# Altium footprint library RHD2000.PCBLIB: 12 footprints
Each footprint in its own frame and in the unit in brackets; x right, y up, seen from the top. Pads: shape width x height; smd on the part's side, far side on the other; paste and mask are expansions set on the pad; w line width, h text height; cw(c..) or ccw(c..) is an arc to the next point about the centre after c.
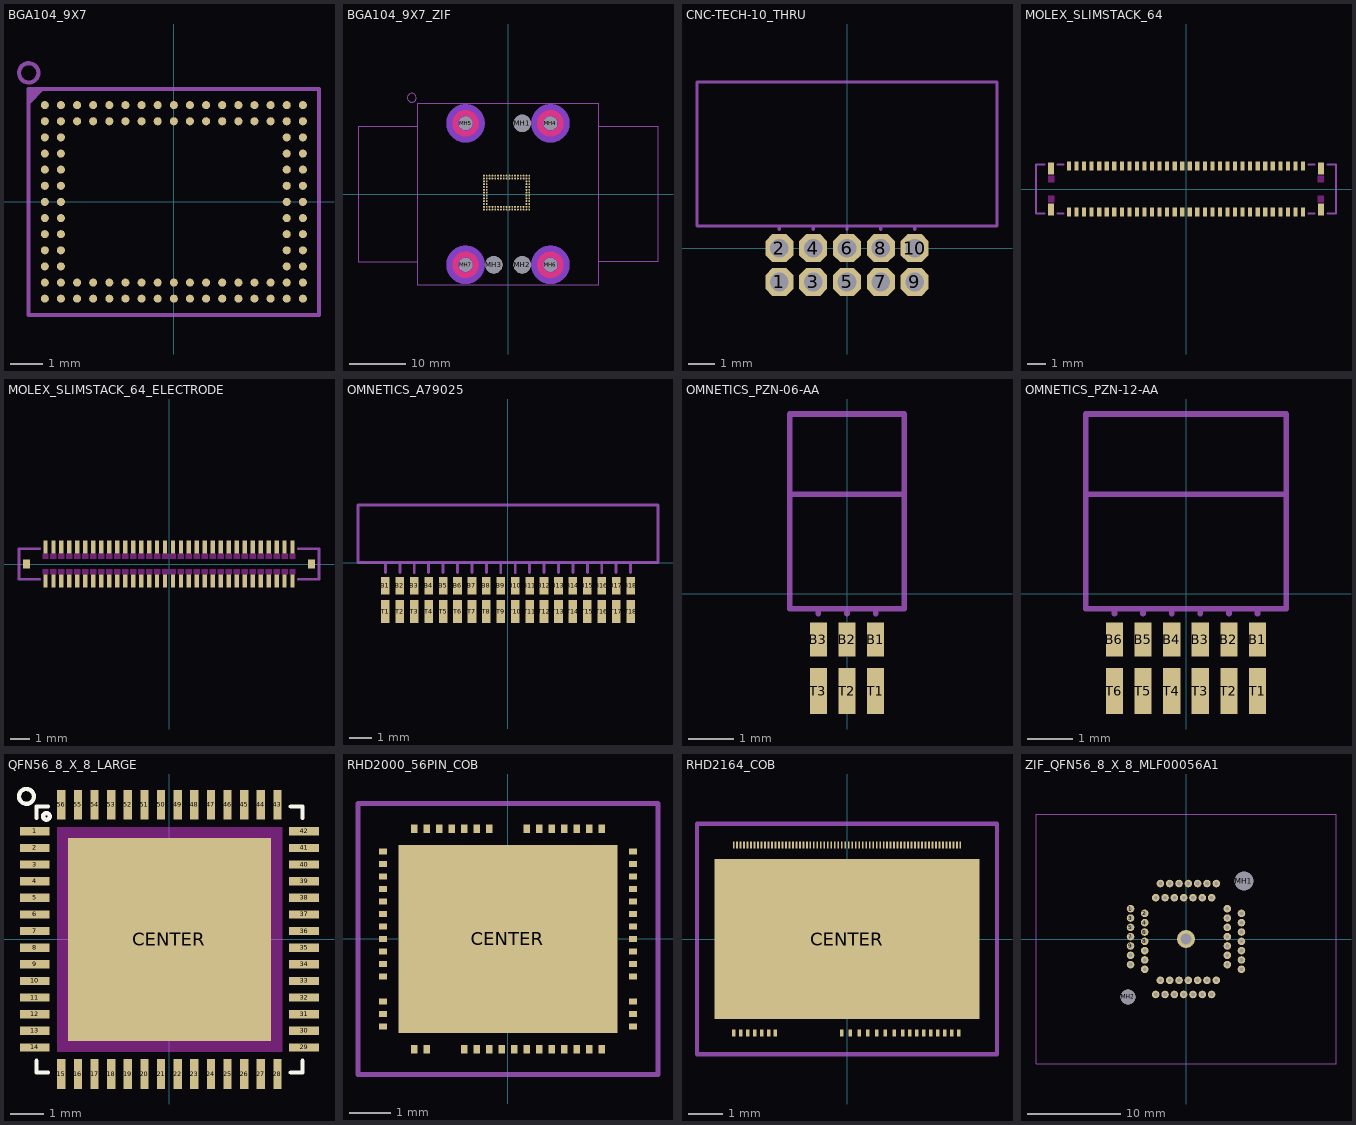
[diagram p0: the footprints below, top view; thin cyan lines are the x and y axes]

## BGA104_9X7 [mm]
pads (104):
  rrect100% 0.25x0.25 smd: A1(-4,3) A2(-3.5,3) A3(-3,3) A4(-2.5,3) A5(-2,3) A6(-1.5,3) A7(-1,3) A8(-0.5,3) A9(0,3) A10(0.5,3) A11(1,3) A12(1.5,3) A13(2,3) A14(2.5,3) A15(3,3) A16(3.5,3) A17(4,3) B1(-4,2.5) B2(-3.5,2.5) B3(-3,2.5) B4(-2.5,2.5) B5(-2,2.5) B6(-1.5,2.5) B7(-1,2.5) B8(-0.5,2.5) B9(0,2.5) B10(0.5,2.5) B11(1,2.5) B12(1.5,2.5) B13(2,2.5) B14(2.5,2.5) B15(3,2.5) B16(3.5,2.5) B17(4,2.5) C1(-4,2) C2(-3.5,2) C16(3.5,2) C17(4,2) D1(-4,1.5) D2(-3.5,1.5) D16(3.5,1.5) D17(4,1.5) E1(-4,1) E2(-3.5,1) E16(3.5,1) E17(4,1) F1(-4,0.5) F2(-3.5,0.5) F16(3.5,0.5) F17(4,0.5) G1(-4,0) G2(-3.5,0) G16(3.5,0) G17(4,0) H1(-4,-0.5) H2(-3.5,-0.5) H16(3.5,-0.5) H17(4,-0.5) J1(-4,-1) J2(-3.5,-1) J16(3.5,-1) J17(4,-1) K1(-4,-1.5) K2(-3.5,-1.5) K16(3.5,-1.5) K17(4,-1.5) L1(-4,-2) L2(-3.5,-2) L16(3.5,-2) L17(4,-2) M1(-4,-2.5) M2(-3.5,-2.5) M3(-3,-2.5) M4(-2.5,-2.5) M5(-2,-2.5) M6(-1.5,-2.5) M7(-1,-2.5) M8(-0.5,-2.5) M9(0,-2.5) M10(0.5,-2.5) M11(1,-2.5) M12(1.5,-2.5) M13(2,-2.5) M14(2.5,-2.5) M15(3,-2.5) M16(3.5,-2.5) M17(4,-2.5) N1(-4,-3) N2(-3.5,-3) N3(-3,-3) N4(-2.5,-3) N5(-2,-3) N6(-1.5,-3) N7(-1,-3) N8(-0.5,-3) N9(0,-3) N10(0.5,-3) N11(1,-3) N12(1.5,-3) N13(2,-3) N14(2.5,-3) N15(3,-3) N16(3.5,-3) N17(4,-3)
tPlace:
  circle w0.127: c-4.5,4 r0.3
  region: -4.5,3.5 -4.5,3 -4,3.5
  lines w0.127: -4.5,-3.5 -4.5,3.5 4.5,3.5 4.5,-3.5 -4.5,-3.5

## BGA104_9X7_ZIF [mil]
pads (111):
  rrect100% 13.39x13.39 smd: A1(-167.32,127.95) A2(-147.64,127.95) A3(-127.95,127.95) A4(-108.27,127.95) A5(-88.58,127.95) A6(-68.9,127.95) A7(-49.21,127.95) A8(-29.53,127.95) A9(-9.84,127.95) A10(9.84,127.95) A11(29.53,127.95) A12(49.21,127.95) A13(68.9,127.95) A14(88.58,127.95) A15(108.27,127.95) A16(127.95,127.95) A17(147.64,127.95) B1(-167.32,108.27) B2(-147.64,108.27) B3(-127.95,108.27) B4(-108.27,108.27) B5(-88.58,108.27) B6(-68.9,108.27) B7(-49.21,108.27) B8(-29.53,108.27) B9(-9.84,108.27) B10(9.84,108.27) B11(29.53,108.27) B12(49.21,108.27) B13(68.9,108.27) B14(88.58,108.27) B15(108.27,108.27) B16(127.95,108.27) B17(147.64,108.27) C1(-167.32,88.58) C2(-147.64,88.58) C16(127.95,88.58) C17(147.64,88.58) D1(-167.32,68.9) D2(-147.64,68.9) D16(127.95,68.9) D17(147.64,68.9) E1(-167.32,49.21) E2(-147.64,49.21) E16(127.95,49.21) E17(147.64,49.21) F1(-167.32,29.53) F2(-147.64,29.53) F16(127.95,29.53) F17(147.64,29.53) G1(-167.32,9.84) G2(-147.64,9.84) G16(127.95,9.84) G17(147.64,9.84) H1(-167.32,-9.84) H2(-147.64,-9.84) H16(127.95,-9.84) H17(147.64,-9.84) J1(-167.32,-29.53) J2(-147.64,-29.53) J16(127.95,-29.53) J17(147.64,-29.53) K1(-167.32,-49.21) K2(-147.64,-49.21) K16(127.95,-49.21) K17(147.64,-49.21) L1(-167.32,-68.9) L2(-147.64,-68.9) L16(127.95,-68.9) L17(147.64,-68.9) M1(-167.32,-88.58) M2(-147.64,-88.58) M3(-127.95,-88.58) M4(-108.27,-88.58) M5(-88.58,-88.58) M6(-68.9,-88.58) M7(-49.21,-88.58) M8(-29.53,-88.58) M9(-9.84,-88.58) M10(9.84,-88.58) M11(29.53,-88.58) M12(49.21,-88.58) M13(68.9,-88.58) M14(88.58,-88.58) M15(108.27,-88.58) M16(127.95,-88.58) M17(147.64,-88.58) N1(-167.32,-108.27) N2(-147.64,-108.27) N3(-127.95,-108.27) N4(-108.27,-108.27) N5(-88.58,-108.27) N6(-68.9,-108.27) N7(-49.21,-108.27) N8(-29.53,-108.27) N9(-9.84,-108.27) N10(9.84,-108.27) N11(29.53,-108.27) N12(49.21,-108.27) N13(68.9,-108.27) N14(88.58,-108.27) N15(108.27,-108.27) N16(127.95,-108.27) N17(147.64,-108.27)
  round 120 hole 120 unplated: MH1(98.43,492.13) MH2(98.43,-492.13) MH3(-98.43,-492.13)
  round 93.74 hole 93.74 unplated: MH4(295.28,492.13) MH5(-295.28,492.13) MH6(295.28,-492.13) MH7(-295.28,-492.13)
Top:
  circle w39.37: c295.28,492.13 r72.64
  circle w39.37: c-295.28,492.13 r72.64
  circle w39.37: c295.28,-492.13 r72.64
  circle w39.37: c-295.28,-492.13 r72.64
Top keep-out:
  circle w94.49: c295.28,492.13 r86.61
  circle w94.49: c-295.28,492.13 r86.61
  circle w94.49: c295.28,-492.13 r86.61
  circle w94.49: c-295.28,-492.13 r86.61
Bottom keep-out:
  circle w94.49: c295.28,492.13 r86.61
  circle w94.49: c-295.28,492.13 r86.61
  circle w94.49: c295.28,-492.13 r86.61
  circle w94.49: c-295.28,-492.13 r86.61
Top Solder:
  region: -610.24,-610.24 610.24,-610.24 610.24,610.24 -610.24,610.24
tPlace:
  circle w5: c-669.29,669.29 r31.12
  lines w5: -629.92,-472.44 -629.92,472.44 ; -629.92,-472.44 -629.92,-629.92 629.92,-629.92 629.92,-472.44 ; -629.92,-472.44 -1043.31,-472.44 -1043.31,472.44 -629.92,472.44 ; -629.92,472.44 -629.92,629.92 629.92,629.92 629.92,472.44 ; 629.92,-472.44 1043.31,-472.44 1043.31,472.44 629.92,472.44 ; 629.92,-472.44 629.92,472.44

## CNC-TECH-10_THRU [mil]
pads (10):
  oct 41.34x41.34 / inner round 38.19 / far side oct 41.34x41.34 hole 27.56: 1(-100,-50) 2(-100,0) 3(-50,-50) 4(-50,0) 5(0,-50) 6(0,0) 7(50,-50) 8(50,0) 9(100,-50) 10(100,0)
tPlace:
  lines w5: -100,27.56 -100,32.68 ; -50,27.56 -50,32.68 ; 0,27.56 0,32.68 ; 50,27.56 50,32.68 ; 100,27.56 100,32.68 ; -100,32.68 -221.46,32.68 -221.46,245.28 221.46,245.28 221.46,32.68 100,32.68 ; -100,32.68 -50,32.68 ; -50,32.68 0,32.68 ; 0,32.68 50,32.68 ; 50,32.68 100,32.68

## MOLEX_SLIMSTACK_64 [mm]
pads (68):
  rect 0.22x0.475 smd: 1(-6.2,-1.213) 2(-5.8,-1.213) 3(-5.4,-1.213) 4(-5,-1.213) 5(-4.6,-1.213) 6(-4.2,-1.213) 7(-3.8,-1.213) 8(-3.4,-1.213) 9(-3,-1.213) 10(-2.6,-1.213) 11(-2.2,-1.213) 12(-1.8,-1.213) 13(-1.4,-1.213) 14(-1,-1.213) 15(-0.6,-1.213) 16(-0.2,-1.213) 17(0.2,-1.213) 18(0.6,-1.213) 19(1,-1.213) 20(1.4,-1.213) 21(1.8,-1.213) 22(2.2,-1.213) 23(2.6,-1.213) 24(3,-1.213) 25(3.4,-1.213) 26(3.8,-1.213) 27(4.2,-1.213) 28(4.6,-1.213) 29(5,-1.213) 30(5.4,-1.213) 31(5.8,-1.213) 32(6.2,-1.213) 33(6.2,1.213) 34(5.8,1.213) 35(5.4,1.213) 36(5,1.213) 37(4.6,1.213) 38(4.2,1.213) 39(3.8,1.213) 40(3.4,1.213) 41(3,1.213) 42(2.6,1.213) 43(2.2,1.213) 44(1.8,1.213) 45(1.4,1.213) 46(1,1.213) 47(0.6,1.213) 48(0.2,1.213) 49(-0.2,1.213) 50(-0.6,1.213) 51(-1,1.213) 52(-1.4,1.213) 53(-1.8,1.213) 54(-2.2,1.213) 55(-2.6,1.213) 56(-3,1.213) 57(-3.4,1.213) 58(-3.8,1.213) 59(-4.2,1.213) 60(-4.6,1.213) 61(-5,1.213) 62(-5.4,1.213) 63(-5.8,1.213) 64(-6.2,1.213)
  rect 0.32x0.65 smd: MECH1(-7.15,1.085) MECH2(-7.15,-1.085) MECH3(7.15,1.085) MECH4(7.15,-1.085)
Top keep-out:
  region: -7.31,0.35 -7.31,0.7 -6.99,0.7 -6.99,0.35
  region: -7.31,-0.7 -7.31,-0.35 -6.99,-0.35 -6.99,-0.7
  region: 6.99,0.35 6.99,0.7 7.31,0.7 7.31,0.35
  region: 6.99,-0.7 6.99,-0.35 7.31,-0.35 7.31,-0.7
tPlace:
  lines w0.127: -7.5,-1.3 -7.95,-1.3 -7.95,1.3 -7.5,1.3 ; -6.8,-1.3 -6.5,-1.3 ; -6.8,1.3 -6.5,1.3 ; 6.5,-1.3 6.8,-1.3 ; 6.5,1.3 6.8,1.3 ; 7.5,-1.3 7.95,-1.3 7.95,1.3 7.5,1.3

## MOLEX_SLIMSTACK_64_ELECTRODE [mm]
pads (66):
  rect 0.22x0.66 smd: 1(-6.2,0.855) 2(-5.8,0.855) 3(-5.4,0.855) 4(-5,0.855) 5(-4.6,0.855) 6(-4.2,0.855) 7(-3.8,0.855) 8(-3.4,0.855) 9(-3,0.855) 10(-2.6,0.855) 11(-2.2,0.855) 12(-1.8,0.855) 13(-1.4,0.855) 14(-1,0.855) 15(-0.6,0.855) 16(-0.2,0.855) 17(0.2,0.855) 18(0.6,0.855) 19(1,0.855) 20(1.4,0.855) 21(1.8,0.855) 22(2.2,0.855) 23(2.6,0.855) 24(3,0.855) 25(3.4,0.855) 26(3.8,0.855) 27(4.2,0.855) 28(4.6,0.855) 29(5,0.855) 30(5.4,0.855) 31(5.8,0.855) 32(6.2,0.855) 33(6.2,-0.855) 34(5.8,-0.855) 35(5.4,-0.855) 36(5,-0.855) 37(4.6,-0.855) 38(4.2,-0.855) 39(3.8,-0.855) 40(3.4,-0.855) 41(3,-0.855) 42(2.6,-0.855) 43(2.2,-0.855) 44(1.8,-0.855) 45(1.4,-0.855) 46(1,-0.855) 47(0.6,-0.855) 48(0.2,-0.855) 49(-0.2,-0.855) 50(-0.6,-0.855) 51(-1,-0.855) 52(-1.4,-0.855) 53(-1.8,-0.855) 54(-2.2,-0.855) 55(-2.6,-0.855) 56(-3,-0.855) 57(-3.4,-0.855) 58(-3.8,-0.855) 59(-4.2,-0.855) 60(-4.6,-0.855) 61(-5,-0.855) 62(-5.4,-0.855) 63(-5.8,-0.855) 64(-6.2,-0.855)
  rect 0.35x0.44 smd: MECH1(-7.15,0) MECH2(7.15,0)
Top keep-out:
  region: -6.35,0.255 -6.35,0.525 -6.05,0.525 -6.05,0.255
  region: -5.95,0.255 -5.95,0.525 -5.65,0.525 -5.65,0.255
  region: -5.55,0.255 -5.55,0.525 -5.25,0.525 -5.25,0.255
  region: -5.15,0.255 -5.15,0.525 -4.85,0.525 -4.85,0.255
  region: -4.75,0.255 -4.75,0.525 -4.45,0.525 -4.45,0.255
  region: -4.35,0.255 -4.35,0.525 -4.05,0.525 -4.05,0.255
  region: -3.95,0.255 -3.95,0.525 -3.65,0.525 -3.65,0.255
  region: -3.55,0.255 -3.55,0.525 -3.25,0.525 -3.25,0.255
  region: -3.15,0.255 -3.15,0.525 -2.85,0.525 -2.85,0.255
  region: -2.75,0.255 -2.75,0.525 -2.45,0.525 -2.45,0.255
  region: -2.35,0.255 -2.35,0.525 -2.05,0.525 -2.05,0.255
  region: -1.95,0.255 -1.95,0.525 -1.65,0.525 -1.65,0.255
  region: -1.55,0.255 -1.55,0.525 -1.25,0.525 -1.25,0.255
  region: -1.15,0.255 -1.15,0.525 -0.85,0.525 -0.85,0.255
  region: -0.75,0.255 -0.75,0.525 -0.45,0.525 -0.45,0.255
  region: -0.35,0.255 -0.35,0.525 -0.05,0.525 -0.05,0.255
  region: 0.05,0.255 0.05,0.525 0.35,0.525 0.35,0.255
  region: 0.45,0.255 0.45,0.525 0.75,0.525 0.75,0.255
  region: 0.85,0.255 0.85,0.525 1.15,0.525 1.15,0.255
  region: 1.25,0.255 1.25,0.525 1.55,0.525 1.55,0.255
  region: 1.65,0.255 1.65,0.525 1.95,0.525 1.95,0.255
  region: 2.05,0.255 2.05,0.525 2.35,0.525 2.35,0.255
  region: 2.45,0.255 2.45,0.525 2.75,0.525 2.75,0.255
  region: 2.85,0.255 2.85,0.525 3.15,0.525 3.15,0.255
  region: 3.25,0.255 3.25,0.525 3.55,0.525 3.55,0.255
  region: 3.65,0.255 3.65,0.525 3.95,0.525 3.95,0.255
  region: 4.05,0.255 4.05,0.525 4.35,0.525 4.35,0.255
  region: 4.45,0.255 4.45,0.525 4.75,0.525 4.75,0.255
  region: 4.85,0.255 4.85,0.525 5.15,0.525 5.15,0.255
  region: 5.25,0.255 5.25,0.525 5.55,0.525 5.55,0.255
  region: 5.65,0.255 5.65,0.525 5.95,0.525 5.95,0.255
  region: 6.05,0.255 6.05,0.525 6.35,0.525 6.35,0.255
  region: 6.05,-0.525 6.05,-0.255 6.35,-0.255 6.35,-0.525
  region: 5.65,-0.525 5.65,-0.255 5.95,-0.255 5.95,-0.525
  region: 5.25,-0.525 5.25,-0.255 5.55,-0.255 5.55,-0.525
  region: 4.85,-0.525 4.85,-0.255 5.15,-0.255 5.15,-0.525
  region: 4.45,-0.525 4.45,-0.255 4.75,-0.255 4.75,-0.525
  region: 4.05,-0.525 4.05,-0.255 4.35,-0.255 4.35,-0.525
  region: 3.65,-0.525 3.65,-0.255 3.95,-0.255 3.95,-0.525
  region: 3.25,-0.525 3.25,-0.255 3.55,-0.255 3.55,-0.525
  region: 2.85,-0.525 2.85,-0.255 3.15,-0.255 3.15,-0.525
  region: 2.45,-0.525 2.45,-0.255 2.75,-0.255 2.75,-0.525
  region: 2.05,-0.525 2.05,-0.255 2.35,-0.255 2.35,-0.525
  region: 1.65,-0.525 1.65,-0.255 1.95,-0.255 1.95,-0.525
  region: 1.25,-0.525 1.25,-0.255 1.55,-0.255 1.55,-0.525
  region: 0.85,-0.525 0.85,-0.255 1.15,-0.255 1.15,-0.525
  region: 0.45,-0.525 0.45,-0.255 0.75,-0.255 0.75,-0.525
  region: 0.05,-0.525 0.05,-0.255 0.35,-0.255 0.35,-0.525
  region: -0.35,-0.525 -0.35,-0.255 -0.05,-0.255 -0.05,-0.525
  region: -0.75,-0.525 -0.75,-0.255 -0.45,-0.255 -0.45,-0.525
  region: -1.15,-0.525 -1.15,-0.255 -0.85,-0.255 -0.85,-0.525
  region: -1.55,-0.525 -1.55,-0.255 -1.25,-0.255 -1.25,-0.525
  region: -1.95,-0.525 -1.95,-0.255 -1.65,-0.255 -1.65,-0.525
  region: -2.35,-0.525 -2.35,-0.255 -2.05,-0.255 -2.05,-0.525
  region: -2.75,-0.525 -2.75,-0.255 -2.45,-0.255 -2.45,-0.525
  region: -3.15,-0.525 -3.15,-0.255 -2.85,-0.255 -2.85,-0.525
  region: -3.55,-0.525 -3.55,-0.255 -3.25,-0.255 -3.25,-0.525
  region: -3.95,-0.525 -3.95,-0.255 -3.65,-0.255 -3.65,-0.525
  region: -4.35,-0.525 -4.35,-0.255 -4.05,-0.255 -4.05,-0.525
  region: -4.75,-0.525 -4.75,-0.255 -4.45,-0.255 -4.45,-0.525
  region: -5.15,-0.525 -5.15,-0.255 -4.85,-0.255 -4.85,-0.525
  region: -5.55,-0.525 -5.55,-0.255 -5.25,-0.255 -5.25,-0.525
  region: -5.95,-0.525 -5.95,-0.255 -5.65,-0.255 -5.65,-0.525
  region: -6.35,-0.525 -6.35,-0.255 -6.05,-0.255 -6.05,-0.525
tPlace:
  lines w0.127: -6.5,-0.77 -7.53,-0.77 -7.53,0.77 -6.5,0.77 ; 6.5,-0.77 7.53,-0.77 7.53,0.77 6.5,0.77

## OMNETICS_A79025 [mil]
pads (36):
  rect 15x30 smd: B1(-212.5,-40) B2(-187.5,-40) B3(-162.5,-40) B4(-137.5,-40) B5(-112.5,-40) B6(-87.5,-40) B7(-62.5,-40) B8(-37.5,-40) B9(-12.5,-40) B10(12.5,-40) B11(37.5,-40) B12(62.5,-40) B13(87.5,-40) B14(112.5,-40) B15(137.5,-40) B16(162.5,-40) B17(187.5,-40) B18(212.5,-40)
  rect 15x40 smd: T1(-212.5,-85) T2(-187.5,-85) T3(-162.5,-85) T4(-137.5,-85) T5(-112.5,-85) T6(-87.5,-85) T7(-62.5,-85) T8(-37.5,-85) T9(-12.5,-85) T10(12.5,-85) T11(37.5,-85) T12(62.5,-85) T13(87.5,-85) T14(112.5,-85) T15(137.5,-85) T16(162.5,-85) T17(187.5,-85) T18(212.5,-85)
tPlace:
  lines w5: -212.5,-17.5 -212.5,0 ; -187.5,-17.5 -187.5,0 ; -162.5,-17.5 -162.5,0 ; -137.5,-17.5 -137.5,0 ; -112.5,-17.5 -112.5,0 ; -87.5,-17.5 -87.5,0 ; -62.5,-17.5 -62.5,0 ; -37.5,-17.5 -37.5,0 ; -12.5,-17.5 -12.5,0 ; 12.5,-17.5 12.5,0 ; 37.5,-17.5 37.5,0 ; 62.5,-17.5 62.5,0 ; 87.5,-17.5 87.5,0 ; 112.5,-17.5 112.5,0 ; 137.5,-17.5 137.5,0 ; 162.5,-17.5 162.5,0 ; 187.5,-17.5 187.5,0 ; 212.5,-17.5 212.5,0 ; -212.5,0 -187.5,0 ; -212.5,0 -260,0 -260,100 260,100 260,0 12.5,0 ; -187.5,0 -162.5,0 ; -162.5,0 -137.5,0 ; -137.5,0 -112.5,0 ; -112.5,0 -87.5,0 ; -87.5,0 -62.5,0 ; -62.5,0 -37.5,0 ; -37.5,0 -12.5,0 ; -12.5,0 12.5,0

## OMNETICS_PZN-06-AA [mil]
pads (6):
  rect 15x30 smd: B1(25,-40) B2(0,-40) B3(-25,-40)
  rect 15x40 smd: T1(25,-85) T2(0,-85) T3(-25,-85)
tPlace:
  lines w5: -25,-17.5 -25,-13 ; 0,-17.5 0,-13 ; 25,-17.5 25,-13 ; -50,87 -50,-13 -25,-13 ; -50,87 -50,157 50,157 50,87 ; -50,87 50,87 ; -25,-13 0,-13 ; 0,-13 25,-13 ; 25,-13 50,-13 50,87

## OMNETICS_PZN-12-AA [mil]
pads (12):
  rect 15x30 smd: B1(62.5,-40) B2(37.5,-40) B3(12.5,-40) B4(-12.5,-40) B5(-37.5,-40) B6(-62.5,-40)
  rect 15x40 smd: T1(62.5,-85) T2(37.5,-85) T3(12.5,-85) T4(-12.5,-85) T5(-37.5,-85) T6(-62.5,-85)
tPlace:
  lines w5: -62.5,-17.5 -62.5,-13 ; -37.5,-17.5 -37.5,-13 ; -12.5,-17.5 -12.5,-13 ; 12.5,-17.5 12.5,-13 ; 37.5,-17.5 37.5,-13 ; 62.5,-17.5 62.5,-13 ; -87.5,87 87.5,87 ; -87.5,87 -87.5,157 87.5,157 87.5,87 ; -87.5,87 -87.5,-13 -62.5,-13 ; -62.5,-13 -37.5,-13 ; -37.5,-13 -12.5,-13 ; -12.5,-13 12.5,-13 ; 12.5,-13 37.5,-13 ; 37.5,-13 62.5,-13 ; 62.5,-13 87.5,-13 87.5,87

## QFN56_8_X_8_LARGE [mm]
pads (57):
  rect 0.9x0.25 smd: 1(-4.05,3.25) 2(-4.05,2.75) 3(-4.05,2.25) 4(-4.05,1.75) 5(-4.05,1.25) 6(-4.05,0.75) 7(-4.05,0.25) 8(-4.05,-0.25) 9(-4.05,-0.75) 10(-4.05,-1.25) 11(-4.05,-1.75) 12(-4.05,-2.25) 13(-4.05,-2.75) 14(-4.05,-3.25) 29(4.05,-3.25) 30(4.05,-2.75) 31(4.05,-2.25) 32(4.05,-1.75) 33(4.05,-1.25) 34(4.05,-0.75) 35(4.05,-0.25) 36(4.05,0.25) 37(4.05,0.75) 38(4.05,1.25) 39(4.05,1.75) 40(4.05,2.25) 41(4.05,2.75) 42(4.05,3.25)
  rect 0.25x0.9 smd: 15(-3.25,-4.05) 16(-2.75,-4.05) 17(-2.25,-4.05) 18(-1.75,-4.05) 19(-1.25,-4.05) 20(-0.75,-4.05) 21(-0.25,-4.05) 22(0.25,-4.05) 23(0.75,-4.05) 24(1.25,-4.05) 25(1.75,-4.05) 26(2.25,-4.05) 27(2.75,-4.05) 28(3.25,-4.05) 43(3.25,4.05) 44(2.75,4.05) 45(2.25,4.05) 46(1.75,4.05) 47(1.25,4.05) 48(0.75,4.05) 49(0.25,4.05) 50(-0.25,4.05) 51(-0.75,4.05) 52(-1.25,4.05) 53(-1.75,4.05) 54(-2.25,4.05) 55(-2.75,4.05) 56(-3.25,4.05)
  rect 6.1x6.1 smd: CENTER(0,0)
Top keep-out:
  region: -3.375,-3.375 -3.375,3.375 3.4,3.375 3.4,-3.375
Top Overlay:
  circle w0.127: c-4.3,4.3 r0.224
  circle w0.127: c-3.7,3.7 r0.1
  lines w0.127: -4,-3.65 -4,-4 -3.65,-4 ; -4,3.65 -4,4 -3.65,4 ; 3.65,-4 4,-4 4,-3.65 ; 3.65,4 4,4 4,3.65
3D body: height 0.85, standoff 0.02, extent -4.5,-4.5 4.5,4.5

## RHD2000_56PIN_COB [mil]
pads (57):
  rect 8x6 smd paste+0: 1(-120,84) 2(-120,72) 3(-120,60) 4(-120,48) 5(-120,36) 6(-120,24) 7(-120,12) 8(-120,0) 9(-120,-12) 10(-120,-24) 11(-120,-36) 12(-120,-60) 13(-120,-72) 14(-120,-84) 29(120,-84) 30(120,-72) 31(120,-60) 32(120,-36) 33(120,-24) 34(120,-12) 35(120,0) 36(120,12) 37(120,24) 38(120,36) 39(120,48) 40(120,60) 41(120,72) 42(120,84)
  rect 6x8 smd paste+0: 15(-90,-106) 16(-78,-106) 17(-42,-106) 18(-30,-106) 19(-18,-106) 20(-6,-106) 21(6,-106) 22(18,-106) 23(30,-106) 24(42,-106) 25(54,-106) 26(66,-106) 27(78,-106) 28(90,-106) 43(90,106) 44(78,106) 45(66,106) 46(54,106) 47(42,106) 48(30,106) 49(18,106) 50(-18,106) 51(-30,106) 52(-42,106) 53(-54,106) 54(-66,106) 55(-78,106) 56(-90,106)
  rect 210x180 smd paste+0: CENTER(0,0)
tPlace:
  lines w5: -144,-130 144,-130 144,130 -144,130 -144,-130

## RHD2164_COB [mil]
pads (90):
  rect 2x8 smd paste+0: 0(-126,108) 1(-122,108) 2(-118,108) 3(-114,108) 4(-110,108) 5(-106,108) 6(-102,108) 7(-98,108) 8(-94,108) 9(-90,108) 10(-86,108) 11(-82,108) 12(-78,108) 13(-74,108) 14(-70,108) 15(-66,108) 16(-62,108) 17(-58,108) 18(-54,108) 19(-50,108) 20(-46,108) 21(-42,108) 22(-38,108) 23(-34,108) 24(-30,108) 25(-26,108) 26(-22,108) 27(-18,108) 28(-14,108) 29(-10,108) 30(-6,108) 31(-2,108) 32(2,108) 33(6,108) 34(10,108) 35(14,108) 36(18,108) 37(22,108) 38(26,108) 39(30,108) 40(34,108) 41(38,108) 42(42,108) 43(46,108) 44(50,108) 45(54,108) 46(58,108) 47(62,108) 48(66,108) 49(70,108) 50(74,108) 51(78,108) 52(82,108) 53(86,108) 54(90,108) 55(94,108) 56(98,108) 57(102,108) 58(106,108) 59(110,108) 60(114,108) 61(118,108) 62(122,108) 63(126,108) A(-130,108) B(130,108)
  rect 4x8 smd paste+0: B1(-130,-108) B2(-122,-108) B3(-114,-108) B4(-106,-108) B5(-98,-108) B6(-90,-108) B7(-82,-108) B8(-6,-108) B9(4,-108) B10(14,-108) B11(24,-108) B12(34,-108) B13(44,-108) B14(54,-108) B15(64,-108) B16(72,-108) B17(80,-108) B18(88,-108) B19(96,-108) B20(104,-108) B21(112,-108) B22(120,-108) B23(128,-108)
  rect 304x184 smd paste+0: CENTER(0,0)
tPlace:
  lines w5: -172,-132 172,-132 172,132 -172,132 -172,-132

## ZIF_QFN56_8_X_8_MLF00056A1 [mil]
pads (59):
  round 32 hole 16.14: 1(-234.45,127.95) 2(-174.41,108.27) 3(-234.45,88.58) 4(-174.41,68.9) 5(-234.45,49.21) 6(-174.41,29.53) 7(-234.45,9.84) 8(-174.41,-9.84) 9(-234.45,-29.53) 10(-174.41,-49.21) 11(-234.45,-68.9) 12(-174.41,-88.58) 13(-234.45,-108.27) 14(-174.41,-127.95) 15(-127.95,-234.45) 16(-108.27,-174.41) 17(-88.58,-234.45) 18(-68.9,-174.41) 19(-49.21,-234.45) 20(-29.53,-174.41) 21(-9.84,-234.45) 22(9.84,-174.41) 23(29.53,-234.45) 24(49.21,-174.41) 25(68.9,-234.45) 26(88.58,-174.41) 27(108.27,-234.45) 28(127.95,-174.41) 29(234.45,-127.95) 30(174.41,-108.27) 31(234.45,-88.58) 32(174.41,-68.9) 33(234.45,-49.21) 34(174.41,-29.53) 35(234.45,-9.84) 36(174.41,9.84) 37(234.45,29.53) 38(174.41,49.21) 39(234.45,68.9) 40(174.41,88.58) 41(234.45,108.27) 42(174.41,127.95) 43(127.95,234.45) 44(108.27,174.41) 45(88.58,234.45) 46(68.9,174.41) 47(49.21,234.45) 48(29.53,174.41) 49(9.84,234.45) 50(-9.84,174.41) 51(-29.53,234.45) 52(-49.21,174.41) 53(-68.9,234.45) 54(-88.58,174.41) 55(-108.27,234.45) 56(-127.95,174.41)
  round 76 hole 47.24: CENTER(0,0)
  round 78.74 hole 78.74 unplated: MH1(245.08,245.08)
  round 62.99 hole 62.99 unplated: MH2(-245.08,-245.08)
tPlace:
  lines w5: -633.86,-527.56 -633.86,527.56 633.86,527.56 633.86,-527.56 -633.86,-527.56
